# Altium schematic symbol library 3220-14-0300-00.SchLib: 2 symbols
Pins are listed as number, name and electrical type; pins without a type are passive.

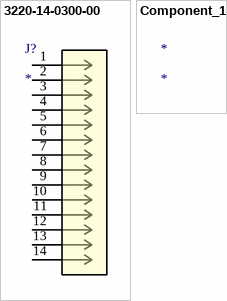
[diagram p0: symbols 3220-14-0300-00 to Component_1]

## 3220-14-0300-00
designator J?
No Description Available; Mfr_Name: CNC Tech
footprint CONN_3220-14-0300-00_CNC
pins: 1, 2, 3, 4, 5, 6, 7, 8, 9, 10, 11, 12, 13, 14

## Component_1
designator *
